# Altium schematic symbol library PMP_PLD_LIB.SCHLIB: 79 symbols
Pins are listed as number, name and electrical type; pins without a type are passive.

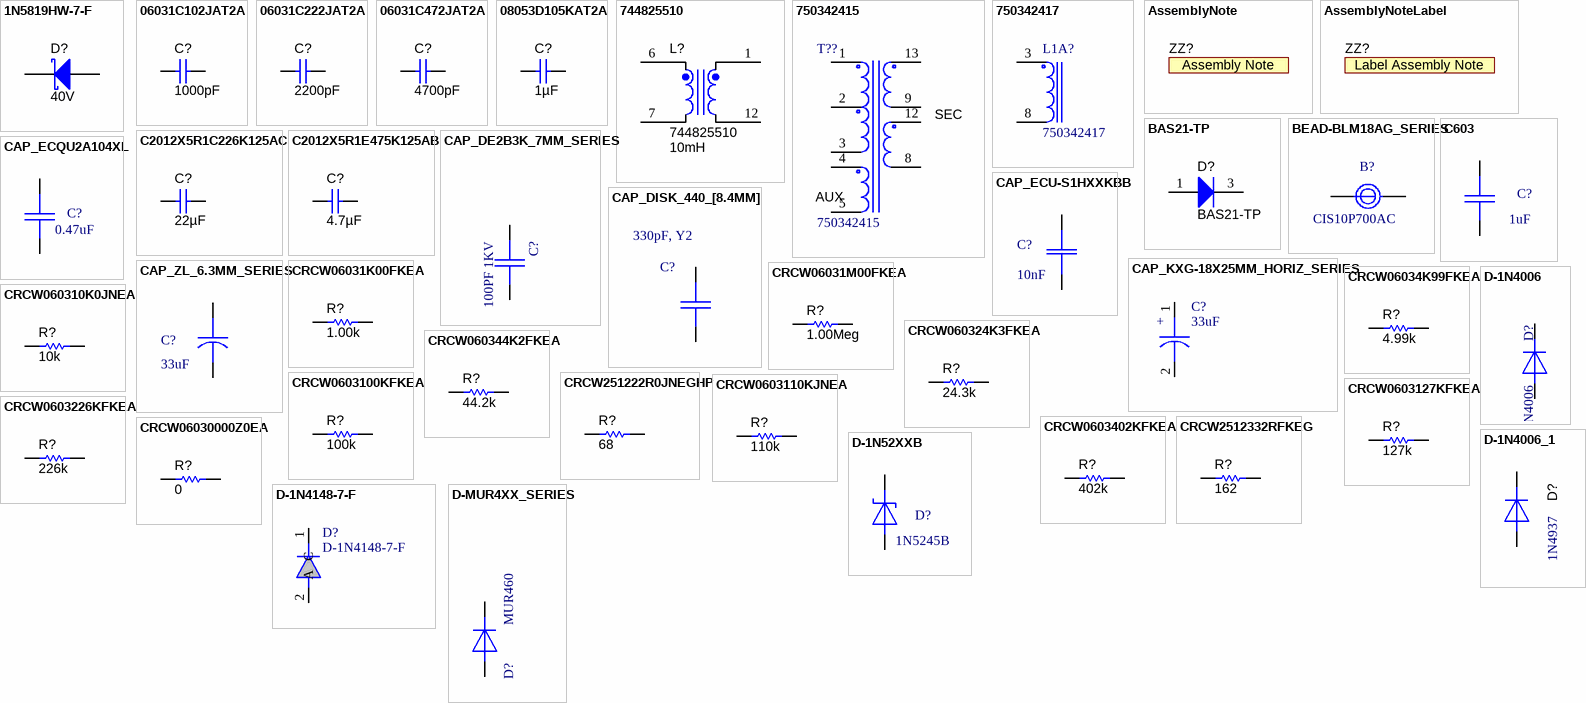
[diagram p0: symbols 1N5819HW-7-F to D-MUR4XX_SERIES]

## 1N5819HW-7-F
designator D?  value 40V  (hidden comment: 1N5819HW-7-F)
Diode, Schottky, 40V, 1A, SOD-123; Manufacturer: Diodes Inc.; U/M: EA; Vf_V: 0.45; Value2: 0.45V; Io_A: 1; Vr_V: 40; TJmax_C: 125
signal-integrity model Diode
simulation model DI_1N5819HW
footprint SOD-123
pins: 1 K, 2 A

## 06031C102JAT2A
designator C?  ValueDisplayed: 1000pF  (hidden comment: 06031C102JAT2A)
CAP, CERM, 1000pF, 100V, +/-5%, X7R, 0603; Manufacturer: AVX; Polarized: N; CompType: Capacitor; U/M: EA; Cap_F: 0.000000001; Tolerance_%: 5; ESR_Ohm: 0.276; Value1: 0.276 ohm; VDC_V: 100; TaMin_C: -55; TaMax_C: 125; Cap_Case: 0603
signal-integrity model Cap
simulation model Cap
footprint 0603
footprint 0603M
footprint 0603L
footprint 0603_HV
footprint 0603S
pins: 1, 2

## 06031C222JAT2A
designator C?  ValueDisplayed: 2200pF  (hidden comment: 06031C222JAT2A)
CAP, CERM, 2200pF, 100V, +/-5%, X7R, 0603; Manufacturer: AVX; Polarized: N; CompType: Capacitor; U/M: EA; Cap_F: 0.0000000022; Tolerance_%: 5; ESR_Ohm: 0.192; Value1: 0.192 ohm; VDC_V: 100; TaMin_C: -55; TaMax_C: 125; Cap_Case: 0603
signal-integrity model Cap
simulation model Cap
footprint 0603
footprint 0603M
footprint 0603L
footprint 0603_HV
footprint 0603S
pins: 1, 2

## 06031C472JAT2A
designator C?  ValueDisplayed: 4700pF  (hidden comment: 06031C472JAT2A)
CAP, CERM, 4700pF, 100V, +/-5%, X7R, 0603; Manufacturer: AVX; Polarized: N; CompType: Capacitor; U/M: EA; Cap_F: 0.0000000047; Tolerance_%: 5; ESR_Ohm: 0.136; Value1: 0.136 ohm; VDC_V: 100; TaMin_C: -55; TaMax_C: 125; Cap_Case: 0603
signal-integrity model Cap
simulation model Cap
footprint 0603
footprint 0603M
footprint 0603L
footprint 0603_HV
footprint 0603S
pins: 1, 2

## 08053D105KAT2A
designator C?  ValueDisplayed: 1µF  (hidden comment: 08053D105KAT2A)
CAP, CERM, 1uF, 25V, +/-10%, X5R, 0805; Manufacturer: AVX; Polarized: N; CompType: Capacitor; U/M: EA; Cap_F: 0.000001; Tolerance_%: 10; ESR_Ohm: 0.012; Value1: 0.012 ohm; VDC_V: 25; TaMin_C: -55; TaMax_C: 85; Cap_Case: 0805
signal-integrity model Cap
simulation model Cap
footprint 0805_HV
footprint 0805
footprint 0805M
footprint 0805L
pins: 1, 2

## 744825510
designator L?  ValueDisplayed: 10mH
Coupled inductor, 10mH, 5A, 0.055 ohm, TH; Manufacturer: Wurth Elektronik eiSos; SymbolCreator: a0799628; Ind_H: 10.0E-3; DCR_ohm: 0.055; Isat: 5
footprint WE-CMB_XL
pins: 1, 6, 7, 12

## 750342415
designator T??
TRANSFOERMER, 856uH, +/-10%, TH, 14-PIN; Manufacturer: WURTH ELEKTRONIK; CompType: TRANSFORMER; SymbolCreator: x0199378
footprint WE_750342415 (TRANSFOERMER, TH)
pins: 1, 2, 3, 4, 5, 8, 9, 12, 13

## 750342417
designator L1A?
TRANSFOERMER, 300uH, +/-10%, TH, 10-PIN; Manufacturer: WURTH ELEKTRONIK; CompType: TRANSFORMER; SymbolCreator: x0199378
footprint WE_750342417 (TRANSFOERMER, TH)
pins: 3, 8

## AssemblyNote
designator ZZ?  (no BOM)
These assemblies are ESD sensitive, ESD precautions shall be observed.; Part_Number: Part Number; SymbolCreator: codlsc; CompType: AssemblyNote
footprint AssemblyNote

## AssemblyNoteLabel
designator ZZ?  (no BOM)
This Assembly Note is for PCB labels only; Part_Number: Part Number; SymbolCreator: a0412235
footprint AssemblyNoteLabel

## BAS21-TP
designator D?
Diode, P-N, 200V, 200A, SOT-23; Manufacturer: Micro Commercial Components; U/M: EA; Vf_V: 1.25; Value2: 1.25V; Io_A: 200; TJmax_C: 150; RJC_CperW: 430
signal-integrity model Model Name (Model Description)
footprint SOT-23
footprint SOT-23M
footprint SOT-23L
pins: 1 A, 3 K

## BEAD-BLM18AG_SERIES
designator B?, comment CIS10P700AC
FERRITE CHIP 70 OHM 4000MA 0603; Manufacturer: Samsung; Second Source: C:\program files\p-cad 2004\pcad_pdf's\Bead BML SERIES.pdf; Reference: \\vette02\pmp_pcb\pcad_pdf's\Bead BML SERIES.pdf; Area: 5.87 mm; Value: 70ohm; PCB DECAL: 0603
footprint xxxx (Footprint not found)
footprint 0603 (0603 from SM-752 data)
pins: 1, 2

## C603
designator C?  value 1uF  (hidden comment: C603)
CAP CER 1UF 25V 10% X7R 0603; Manufacturer: Kemet; PartNumber: C0603C105K3RACTU; Area: 5650
footprint C603
pins: 1, 2

## C2012X5R1C226K125AC
designator C?  ValueDisplayed: 22µF  (hidden comment: C2012X5R1C226K125AC)
CAP, CERM, 22uF, 16V, +/-10%, X5R, 0805; Manufacturer: TDK; Polarized: N; CompType: Capacitor; U/M: EA; Cap_F: 0.000022; Tolerance_%: 10; Value1: Unknown; VDC_V: 16; TaMin_C: -55; TaMax_C: 85; Cap_Case: 0805
signal-integrity model Cap
simulation model Cap
footprint 0805_HV
footprint 0805
footprint 0805M
footprint 0805L
pins: 1, 2

## C2012X5R1E475K125AB
designator C?  ValueDisplayed: 4.7µF  (hidden comment: C2012X5R1E475K125AB)
CAP, CERM, 4.7uF, 25V, +/-10%, X5R, 0805; Manufacturer: TDK; Polarized: N; CompType: Capacitor; U/M: EA; Cap_F: 0.0000047; Tolerance_%: 10; Value1: Unknown; VDC_V: 25; TaMin_C: -55; TaMax_C: 85; Cap_Case: 0805
signal-integrity model Cap
simulation model Cap
footprint 0805_HV
footprint 0805
footprint 0805M
footprint 0805L
pins: 1, 2

## CAP_DE2B3K_7MM_SERIES
designator C?  value 100PF 1KV  (hidden comment: CAP_DE2B3K_7MM_SERIES)
CAP CER 100PF 1KV 10% RADIAL; PartNumber: DEBB33A101KP2A; Manufacturer: muRata; Area: 48.60 mm; PCB DECAL: CAP_200MIL-A
footprint CAP_200MIL-A
pins: 1, 2

## CAP_DISK_440_[8.4MM]
designator C?  value 330pF, Y2  (hidden comment: CAP_DISK_440_[8.4MM])
CAP CER 330PF 300VAC 10% RADIAL; Manufacturer: Vishay; Part_Number: VY2331K29Y5SS63V7; PartNumber: Part Number; Description: Capacitor, 300VAC, X1Y2, ±10%; Area: 103.50 mm; Reference: \\vette02\pmp_pcb\pcad_pdf's\440l.pdf; Second_Source: C:\program files\p-cad 2004\pcad_pdf's\ABB0000CE12.pdf; Type: CAP_DISK_720; PCB DECAL: CAP_DISK_8.4MM; Second Source: C:\program files\p-cad2004pcad_pdf's\440l.pdf
footprint CAP_DISK_8.4MM
pins: 1, 2

## CAP_ECQU2A104XL
designator C?, comment value 0.47uF  (hidden comment: R46KI347050P1M)
CAP FILM 0.47UF 560VDC RADIAL; Manufacturer: Kemet; PCB DECAL: 18.00mm x 9.00mm; Area: 97500
footprint CAP_591MIL
pins: 1, 2

## CAP_ECU-S1HXXKBB
designator C?  value 10nF  (hidden comment: CAP_ECU-S1HXXKBB)
CAP CER 10000PF 1KV 20% RADIAL; Manufacturer: Vishay; PartNumber: S103M47Z5UN63J7R; Part_Number: Part Number; Area: 43200; Reference: \\vette02\pmp_pcb\pcad_pdf's\panasonic_ECQu.pdf; Second_Source: C:\program files\p-cad 2004\pcad_pdf's\panasonic_ECQu.pdf; PCB DECAL: CAP_200MIL
footprint CAP_200MIL
pins: 1, 2

## CAP_KXG-18X25MM_HORIZ_SERIES
designator C?, comment 33uF
Capacitor, Electrolytic, -40 to +105 °C; PartNumber: EKXG451ELL330MM20S; Manufacturer: Nippon; Area: 667.40 mm; Value: xx uH
footprint CAP_18X25MM7.5_PITCH_HORIZ
pins: 1, 2
1 alternate drawing of the same symbol

## CAP_ZL_6.3MM_SERIES
designator C?  value 33uF  (hidden comment: CAP_ZL_6.3MM_SERIES)
CAP ALUM 33UF 35V 20% RADIAL; Manufacturer: Rubycon; Part_Number: 35YXJ33M5X11; PartNumber: Part Number; Area: 70,686; Type: CAP_ZL_6.3MM SERIES; PCB DECAL: CAP_ZL-6.3MM
footprint CAP_ZL-6.3MM
pins: 1, 2

## CRCW06031K00FKEA
designator R?  value 1.00k  (hidden comment: CRCW06031K00FKEA)
RES, 1.00k ohm, 1%, 0.1W, 0603; Manufacturer: Vishay-Dale; CompType: Resistor; Res_ohm: 1000; Value_Code: 1k00; Tolerance_%: 1; Power_W: 0.1; VDC_V: 75; TempCo: 100 ppm/C; EIA_Code: E96; U/M: EA
signal-integrity model Resistor
simulation model Resistor
footprint 0603
footprint 0603M
footprint 0603L
footprint 0603_HV
footprint 0603S
pins: 1, 2

## CRCW06031M00FKEA
designator R?  value 1.00Meg  (hidden comment: CRCW06031M00FKEA)
RES, 1.00Meg ohm, 1%, 0.1W, 0603; Manufacturer: Vishay-Dale; CompType: Resistor; Res_ohm: 1000000; Value_Code: 1M00; Tolerance_%: 1; Power_W: 0.1; VDC_V: 75; TempCo: 100 ppm/C; EIA_Code: E96; U/M: EA
signal-integrity model Resistor
simulation model Resistor
footprint 0603
footprint 0603M
footprint 0603L
footprint 0603_HV
footprint 0603S
pins: 1, 2

## CRCW06034K99FKEA
designator R?  value 4.99k  (hidden comment: CRCW06034K99FKEA)
RES, 4.99k ohm, 1%, 0.1W, 0603; Manufacturer: Vishay-Dale; CompType: Resistor; Res_ohm: 4990; Value_Code: 4k99; Tolerance_%: 1; Power_W: 0.1; VDC_V: 75; TempCo: 100 ppm/C; EIA_Code: E96; U/M: EA
signal-integrity model Resistor
simulation model Resistor
footprint 0603
footprint 0603M
footprint 0603L
footprint 0603_HV
footprint 0603S
pins: 1, 2

## CRCW060310K0JNEA
designator R?  value 10k  (hidden comment: CRCW060310K0JNEA)
RES, 10k ohm, 5%, 0.1W, 0603; Manufacturer: Vishay-Dale; CompType: Resistor; Res_ohm: 10000; Value_Code: 10k0; Tolerance_%: 5; Power_W: 0.1; VDC_V: 75; TempCo: 200 ppm/C; EIA_Code: E24; U/M: EA
signal-integrity model Resistor
simulation model Resistor
footprint 0603
footprint 0603M
footprint 0603L
footprint 0603_HV
footprint 0603S
pins: 1, 2

## CRCW060324K3FKEA
designator R?  value 24.3k  (hidden comment: CRCW060324K3FKEA)
RES, 24.3k ohm, 1%, 0.1W, 0603; Manufacturer: Vishay-Dale; CompType: Resistor; Res_ohm: 24300; Value_Code: 24k3; Tolerance_%: 1; Power_W: 0.1; VDC_V: 75; TempCo: 100 ppm/C; EIA_Code: E96; U/M: EA
signal-integrity model Resistor
simulation model Resistor
footprint 0603
footprint 0603M
footprint 0603L
footprint 0603_HV
footprint 0603S
pins: 1, 2

## CRCW060344K2FKEA
designator R?  value 44.2k  (hidden comment: CRCW060344K2FKEA)
RES, 44.2k ohm, 1%, 0.1W, 0603; Manufacturer: Vishay-Dale; CompType: Resistor; Res_ohm: 44200; Value_Code: 44k2; Tolerance_%: 1; Power_W: 0.1; VDC_V: 75; TempCo: 100 ppm/C; EIA_Code: E96; U/M: EA
signal-integrity model Resistor
simulation model Resistor
footprint 0603
footprint 0603M
footprint 0603L
footprint 0603_HV
footprint 0603S
pins: 1, 2

## CRCW251222R0JNEGHP
designator R?, comment value 68  (hidden comment: RHC2512FT68R0)
RES 68 OHM 2W 1% 2512; Manufacturer: Stackpole Electronics Inc; CompType: Resistor; Tolerance_%: 1
signal-integrity model Resistor
simulation model Resistor
footprint 2512M
footprint 2512L
footprint 2512
pins: 1, 2

## CRCW0603100KFKEA
designator R?  value 100k  (hidden comment: CRCW0603100KFKEA)
RES, 100k ohm, 1%, 0.1W, 0603; Manufacturer: Vishay-Dale; CompType: Resistor; Res_ohm: 100000; Tolerance_%: 1; Power_W: 0.1; VDC_V: 75; TempCo: 100 ppm/C; EIA_Code: E96; U/M: EA
signal-integrity model Resistor
simulation model Resistor
footprint 0603
footprint 0603M
footprint 0603L
footprint 0603_HV
footprint 0603S
pins: 1, 2

## CRCW0603110KJNEA
designator R?  value 110k  (hidden comment: CRCW0603110KJNEA)
RES, 110k ohm, 5%, 0.1W, 0603; Manufacturer: Vishay-Dale; CompType: Resistor; Res_ohm: 110000; Tolerance_%: 5; Power_W: 0.1; VDC_V: 75; TempCo: 200 ppm/C; EIA_Code: E24; U/M: EA
signal-integrity model Resistor
simulation model Resistor
footprint 0603
footprint 0603M
footprint 0603L
footprint 0603_HV
footprint 0603S
pins: 1, 2

## CRCW0603127KFKEA
designator R?  value 127k  (hidden comment: CRCW0603127KFKEA)
RES, 127k ohm, 1%, 0.1W, 0603; Manufacturer: Vishay-Dale; CompType: Resistor; Res_ohm: 127000; Tolerance_%: 1; Power_W: 0.1; VDC_V: 75; TempCo: 100 ppm/C; EIA_Code: E96; U/M: EA
signal-integrity model Resistor
simulation model Resistor
footprint 0603
footprint 0603M
footprint 0603L
footprint 0603_HV
footprint 0603S
pins: 1, 2

## CRCW0603226KFKEA
designator R?  value 226k  (hidden comment: CRCW0603226KFKEA)
RES, 226k ohm, 1%, 0.1W, 0603; Manufacturer: Vishay-Dale; CompType: Resistor; Res_ohm: 226000; Tolerance_%: 1; Power_W: 0.1; VDC_V: 75; TempCo: 100 ppm/C; EIA_Code: E96; U/M: EA
signal-integrity model Resistor
simulation model Resistor
footprint 0603
footprint 0603M
footprint 0603L
footprint 0603_HV
footprint 0603S
pins: 1, 2

## CRCW0603402KFKEA
designator R?  value 402k  (hidden comment: CRCW0603402KFKEA)
RES, 402k ohm, 1%, 0.1W, 0603; Manufacturer: Vishay-Dale; CompType: Resistor; Res_ohm: 402000; Tolerance_%: 1; Power_W: 0.1; VDC_V: 75; TempCo: 100 ppm/C; EIA_Code: E96; U/M: EA
signal-integrity model Resistor
simulation model Resistor
footprint 0603
footprint 0603M
footprint 0603L
footprint 0603_HV
footprint 0603S
pins: 1, 2

## CRCW2512332RFKEG
designator R?, comment value 162  (hidden comment: CRCW2512162RFKEGHP)
RES 162 OHM 1.5W 1% 2512 SMD; Manufacturer: Vishay-Dale; CompType: Resistor; Value_Code: 162R; Tolerance_%: 1; EIA_Code: E96; U/M: EA
signal-integrity model Resistor
simulation model Resistor
footprint 2512M
footprint 2512L
footprint 2512
pins: 1, 2

## CRCW06030000Z0EA
designator R?  value 0  (hidden comment: CRCW06030000Z0EA)
RES, 0 ohm, 5%, 0.1W, 0603; Manufacturer: Vishay-Dale; CompType: Resistor; Value_Code: 0000; Tolerance_%: 5; Power_W: 0.1; VDC_V: 75; TempCo: 200 ppm/C; EIA_Code: E24; U/M: EA
signal-integrity model Resistor
simulation model Resistor
footprint 0603
footprint 0603M
footprint 0603L
footprint 0603_HV
footprint 0603S
pins: 1, 2

## D-1N52XXB
designator D?  value 1N5245B  (hidden comment: D-1N52XXB)
DIODE, Zener, 15V, .5W, 5%; PartNumber: 1N5245BTR; Manufacturer: Fairchild; Area: 64900; PCB DECAL: DO-35; Second Source: C:\program files\p-cad 2004\pcad_pdf's\1N52xx_DO-35.pdf; Reference: \\vette02\pmp_pcb\pcad_pdf's\1N52xx_DO-35.pdf
footprint DO-35
pins: 1 C, 2 A

## D-1N4006
designator D?  value 1N4006  (hidden comment: D-1N4006)
Diode, Rectifier, 800V, 1A; PartNumber: 1N4006-T; Manufacturer: Diodes; Part_Number: Part Number; Second Source: C:\program files\p-cad 2004\pcad_pdf's\1N400x.pdf; Reference: \\vette02\pmp_pcb\pcad_pdf's\1N400x.pdf; Area: 54000; PCB DECAL: DO-41
footprint DO-41 (diode)
pins: 1 C, 2 A

## D-1N4006_1
designator D?, comment value 1N4937  (hidden comment: D-1N4006)
Diode, Fast, 600V, 1A; Manufacturer: Fairchild; Part_Number: Part Number; Second Source: C:\program files\p-cad 2004\pcad_pdf's\1N400x.pdf; Reference: \\vette02\pmp_pcb\pcad_pdf's\1N400x.pdf; Area: 54000; PCB DECAL: DO-41_VERT
pins: 1 A, 2 C

## D-1N4148-7-F
designator D?
Diode, Signal, 300-mA, 75-V, 350-mW; PartNumber: 1N4148W-7-F; Manufacturer: Diodes; Area: 13300; Value: 1N4148W-7-F
footprint D_SOD123
pins: 1 C, 2 A

## D-MUR4XX_SERIES
designator D?  value MUR460  (hidden comment: D-MUR4XX_SERIES)
Diode, Utrafast, Power Rectifier, 600V, 4A; PartNumber: MUR460RLG; Manufacturer: OnSemi; Part_Number: Part Number; Second Source: C:\program files\p-cad 2004\pcad_pdf's\MUR4xx series.pdf; Reference: \\vette02\pmp_pcb\pcad_pdf's\MUR4xx series.pdf; Area: 96800; PCB DECAL: DO-201AD
footprint DO-201AD (Vishay dimensions)
pins: 1, 2

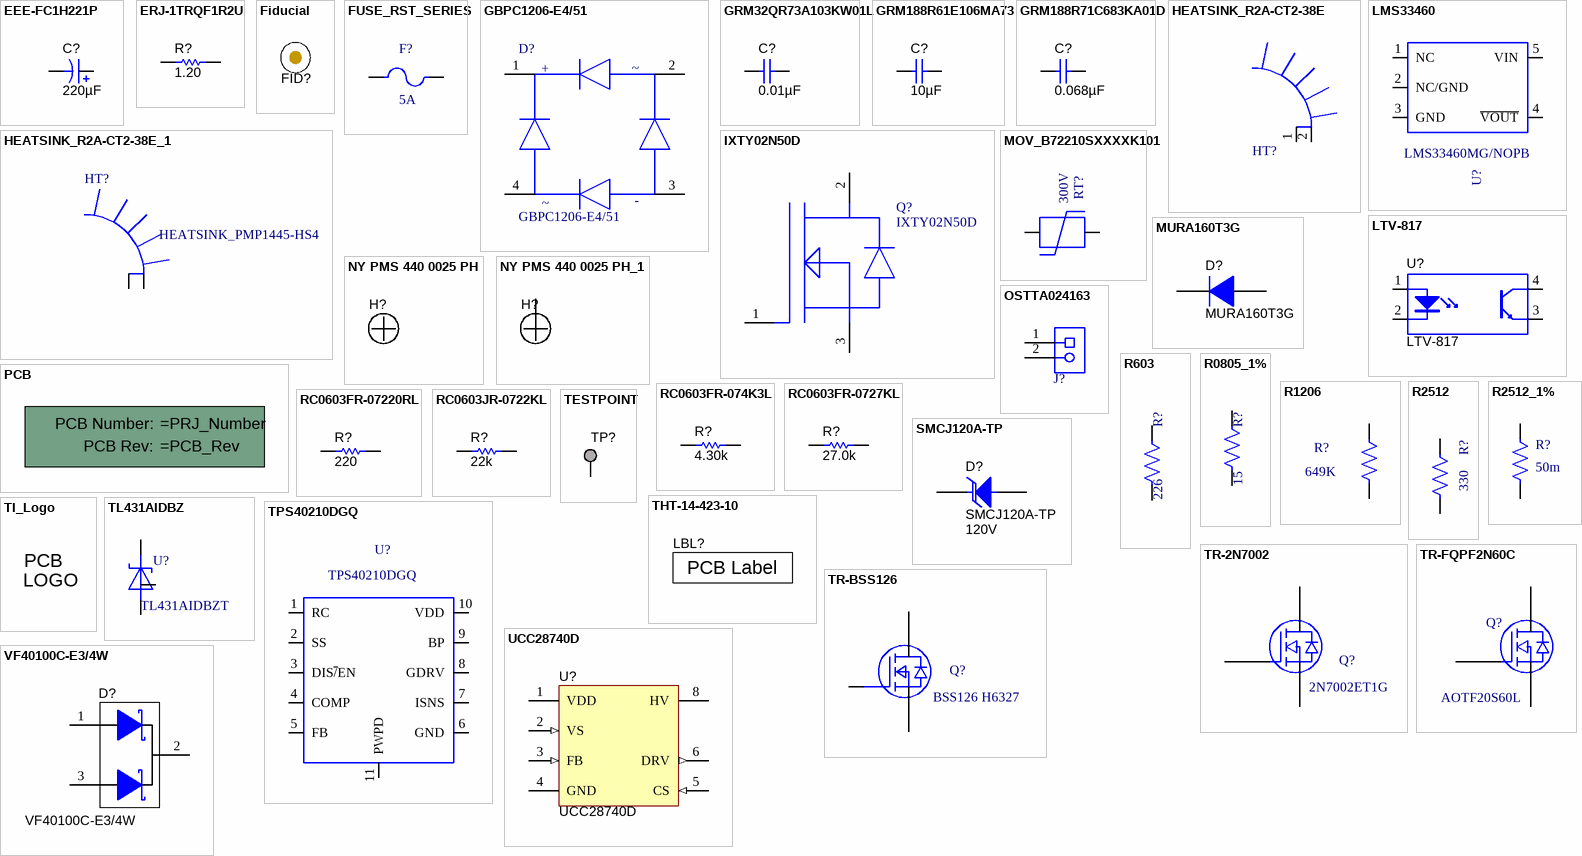
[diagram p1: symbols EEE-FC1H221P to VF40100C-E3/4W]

## EEE-FC1H221P
designator C?  ValueDisplayed: 220µF  (hidden comment: EEE-FC1H221P)
CAP, AL, 220uF, 50V, +/-20%, 0.3 ohm, SMD; Manufacturer: Panasonic; Polarized: Y; CompType: Capacitor; U/M: EA; Cap_F: 0.00022; Tolerance_%: 20; Value1: 0.3 ohm; VDC_V: 50; ESR_Ohm: 0.3; IRMS_A: 0.5; TaMin_C: -40; TaMax_C: 105; Cap_Case: G
signal-integrity model Cap
simulation model Cap
footprint SM_RADIAL_G
pins: 1 +, 2 -

## ERJ-1TRQF1R2U
designator R?  value 1.20  (hidden comment: ERJ-1TRQF1R2U)
RES, 1.20 ohm, 1%, 1W, 2512; Manufacturer: Panasonic; CompType: Resistor; Res_ohm: 1.2; Value_Code: 1R20; Tolerance_%: 1; TempCo: 100 ppm/C; U/M: EA
signal-integrity model Resistor
simulation model Resistor
footprint 2512M
footprint 2512L
footprint 2512
pins: 1, 2

## Fiducial
designator FID?  (value not drawn)
Fiducial mark.  There is nothing to buy or mount.; Part_Number: Part Number; SymbolCreator: codlsc
footprint Fiducial10-30
footprint Fiducial10-20
footprint Fiducial15-30
footprint Fiducial20-40
footprint Fiducial6.4-20
footprint Fiducial10-30_Panel

## FUSE_RST_SERIES
designator F?  value 5A  (hidden comment: FUSE_RST_SERIES)
FUSE SLOW 250VAC 5A RADIAL; Manufacturer: BEL; PartNumber: RST 5; Area: 43.2 mm; PCB DECAL: FUSE_4X8.5-5.08P; Reference: \\vette02\pmp_pcb\pcad_pdf's\RST.pdf; Second Source: C:\program files\p-cad 2004\pcad_pdf's\RST.pdf
footprint FUSE_4X8.5-5.08P
pins: 1, 2

## GBPC1206-E4/51
designator D?
DISCRETE, RECTIFIER BRIDGE 12A 600V, GBPC-4; Manufacturer: VISHAY SEMICONDUCTOR; SymbolCreator: X0199378
footprint MODULE_GBPC1206W-E4-51
pins: 1, 2, 3, 4

## GRM32QR73A103KW01L
designator C?  ValueDisplayed: 0.01µF  (hidden comment: GRM32QR73A103KW01L)
CAP, CERM, 0.01uF, 1000V, +/-10%, X7R, 1210; Manufacturer: MuRata; Polarized: N; CompType: Capacitor; U/M: EA; Cap_F: 0.00000001; Tolerance_%: 10; Value1: Unknown; VDC_V: 1000; TaMin_C: -55; TaMax_C: 125; Cap_Case: 1210
signal-integrity model Cap
simulation model Cap
footprint 1210
footprint 1210M
footprint 1210L
pins: 1, 2

## GRM188R61E106MA73
designator C?  ValueDisplayed: 10µF  (hidden comment: GRM188R61E106MA73)
CAP, CERM, 10uF, 25V, +/-20%, X5R, 0603; Manufacturer: MuRata; Polarized: N; CompType: Capacitor; U/M: EA; Cap_F: 0.00001; Tolerance_%: 20; Value1: Unknown; VDC_V: 25; TaMin_C: -55; TaMax_C: 85; Cap_Case: 0603
signal-integrity model Cap
simulation model Cap
footprint 0603
footprint 0603M
footprint 0603L
footprint 0603_HV
footprint 0603S
pins: 1, 2

## GRM188R71C683KA01D
designator C?  ValueDisplayed: 0.068µF  (hidden comment: GRM188R71C683KA01D)
CAP, CERM, 0.068uF, 16V, +/-10%, X7R, 0603; Manufacturer: MuRata; Polarized: N; CompType: Capacitor; U/M: EA; Cap_F: 0.000000068; Tolerance_%: 10; Value1: Unknown; VDC_V: 16; TaMin_C: -55; TaMax_C: 125; Cap_Case: 0603
signal-integrity model Cap
simulation model Cap
footprint 0603
footprint 0603M
footprint 0603L
footprint 0603_HV
footprint 0603S
pins: 1, 2

## HEATSINK_R2A-CT2-38E
designator HT?, comment HEATSINK_PMP1445-HS4  (value not drawn)
Heatsink, TO-220; Manufacturer: Ohmite; PartNumber: R2A-CT2-38E; PartNumber: Part Number; Value: R2A-CT2-38E
footprint R2A-CT2-38E-ND (HEATSINK FOR TO-220)
pins: 1, 2

## HEATSINK_R2A-CT2-38E_1
designator HT?, comment HEATSINK_PMP1445-HS4
Heatsink, TO-220; Manufacturer: Ohmite; PartNumber: R2A-CT2-38E; PartNumber: Part Number; Value: R2A-CT2-38E
footprint R2A-CT2-38E-ND (HEATSINK FOR TO-220)
pins: 1, 2

## IXTY02N50D
designator Q?
DISCRETE, MOSFET N-CH 500V 200MA, DPAK; Manufacturer: IXYS; SymbolCreator: x0199378
footprint TO228P991X238-3N
pins: 1 G, 2 D, 3 S

## LMS33460
designator U?  value LMS33460MG/NOPB  (hidden comment: LMS33460)
IC DETECTOR UNDER VOLT 3V SC70-5; Manufacturer: TI; Second Source: C:\program files\p-cad 2004\pcad_pdf's\lms33460[1].pdf; Reference: \\vette02\pmp_pcb\pcad_pdf's\lms33460[1].pdf; Area: 12.05 mm; PCB DECAL: SC-70-5
footprint SC-70-5
pins: 1 NC, 2 NC/GND, 3 GND, 4 ~{VOUT}, 5 VIN

## LTV-817
designator U?
Opto-Isolator, 1 Channel, TH; Manufacturer: Lite-On; CompType: OPTOCOUPLER; U/M: EA
footprint DIP762W60P254L460H350Q4B
pins: 1 A, 2 K, 3 E, 4 C

## MOV_B72210SXXXXK101
designator RT?  value 300V  (hidden comment: MOV_B72210SXXXXK101)
MOV, 300V; Manufacturer: Bourns; Part_Number: MOV-10D471KTR; Area: 85,500; PCB DECAL: DISK-472
footprint DISK-472
pins: 1, 2

## MURA160T3G
designator D?
Diode, Ultrafast, 600V, 1A, SMA; Manufacturer: ON Semiconductor; U/M: EA; Vf_V: 1.05; Value2: 1.05V; Io_A: 1; Vr_V: 600; TJmax_C: 175
signal-integrity model Diode
simulation model Dmura160t3
footprint SMA
pins: 1 K, 2 A

## NY PMS 440 0025 PH
designator H?
Mounting Hole M3 3.5mm; Manufacturer: STD; CompType: Hardware; U/M: EA
footprint NY PMS 440 0025 PH

## NY PMS 440 0025 PH_1
designator H?
Mounting Hole M3 3.5mm; Manufacturer: STD; CompType: Hardware; U/M: EA
footprint NY PMS 440 0025 PH
pins: 1

## OSTTA024163
designator J?  (value not drawn)
Terminal Block, 2x1, 5.08mm, TH; PartNumber: OSTTC022162; Manufacturer: On-Shore Technology; SymbolCreator: a0412235; U/M: EA
footprint On-Shore_OSTTA024163
pins: 1, 2

## PCB
designator !PCB?  (mechanical)
Printed Circuit Board; Manufacturer: Any; Part_Number: Part Number; SymbolCreator: a0412235; CompType: PCB
1 alternate drawing of the same symbol

## R603
designator R?  value 226  (hidden comment: R603)
RES 226 OHM 1/10W 1% 0603 SMD; Part_Number: RC0603FR-07226RL; Manufacturer: Yageo; Area: 5650
footprint R603
pins: 1, 2

## R0805_1%
designator R?  value 15  (hidden comment: R0805_1%)
RES 15.0 OHM 1/8W 1% 0805 SMD; Part_Number: RC0805FR-0715RL; Manufacturer: Yageo; Area: 15,300; PCB DECAL: R0805
footprint R0805
pins: 1, 2

## R1206
designator R?  value 649K  (hidden comment: R1206)
RES 649K OHM 1/4W 1% 1206 SMD; Manufacturer: Yageo; PartNumber: RC1206FR-07649KL; Area: 15390
footprint r1206
pins: 1, 2

## R2512
designator R?  value 330  (hidden comment: R2512)
RES 330 OHM 1W 5% 2512; Manufacturer: Samsung; PartNumber: RC6432J331CS; Area: 35100
footprint R2512
pins: 1, 2

## R2512_1%
designator R?  value 50m  (hidden comment: R2512_1%)
RES 0.05 OHM 1W 1% 2512 SMD; Part_Number: LRMAM2512-R05FT4; Manufacturer: TT/Welwyn; PartNumber: LRMAM2512-R02FT4; Area: 56000; PCB DECAL: R2512; Second Source: C:\program files\p-cad 2004\pcad_pdf's\SML-LXR1206USBC-TR[1].pdf; Reference: \\vette02\pmp_pcb\pcad_pdf's\SML-LXR1206USBC-TR[1].pdf
footprint R2512
pins: 1, 2

## RC0603FR-074K3L
designator R?  value 4.30k  (hidden comment: RC0603FR-074K3L)
RES, 4.30k ohm, 1%, 0.1W, 0603; Manufacturer: Yageo America; CompType: Resistor; Res_ohm: 4300; Value_Code: 4k30; Tolerance_%: 1; Power_W: 0.1; VDC_V: 150; TempCo: 200 ppm/C; U/M: EA
signal-integrity model Resistor
simulation model Resistor
footprint 0603
footprint 0603M
footprint 0603L
footprint 0603_HV
footprint 0603S
pins: 1, 2

## RC0603FR-0727KL
designator R?  value 27.0k  (hidden comment: RC0603FR-0727KL)
RES, 27.0k ohm, 1%, 0.1W, 0603; Manufacturer: Yageo America; CompType: Resistor; Res_ohm: 27000; Value_Code: 27k0; Tolerance_%: 1; Power_W: 0.1; VDC_V: 150; TempCo: 200 ppm/C; U/M: EA
signal-integrity model Resistor
simulation model Resistor
footprint 0603
footprint 0603M
footprint 0603L
footprint 0603_HV
footprint 0603S
pins: 1, 2

## RC0603FR-07220RL
designator R?  value 220  (hidden comment: RC0603FR-07220RL)
RES, 220 ohm, 1%, 0.1W, 0603; Manufacturer: Yageo America; CompType: Resistor; Value_Code: 220R; Tolerance_%: 1; Power_W: 0.1; VDC_V: 150; TempCo: 200 ppm/C; U/M: EA
signal-integrity model Resistor
simulation model Resistor
footprint 0603
footprint 0603M
footprint 0603L
footprint 0603_HV
footprint 0603S
pins: 1, 2

## RC0603JR-0722KL
designator R?  value 22k  (hidden comment: RC0603JR-0722KL)
RES, 22k ohm, 5%, 0.1W, 0603; Manufacturer: Yageo America; CompType: Resistor; Res_ohm: 22000; Value_Code: 22k0; Tolerance_%: 5; Power_W: 0.1; VDC_V: 50; TempCo: 100 ppm/C; EIA_Code: E24; U/M: EA
signal-integrity model Resistor
simulation model Resistor
footprint 0603
footprint 0603M
footprint 0603L
footprint 0603_HV
footprint 0603S
pins: 1, 2

## SMCJ120A-TP
designator D?  value 120V
Diode, TVS, Uni, 120V, 1500W, SMC; Manufacturer: Micro Commercial Components; U/M: EA; Power_W: 1500; Vr_V: 120
footprint SMC
pins: 1 K, 2 A

## TESTPOINT
designator TP?  (value not drawn)  (no BOM)
TEST POINT.  No entry in BOM.; PartNumber: Part Number
footprint TESTPOINT
footprint TP_VIA_018RND008
pins: 1

## THT-14-423-10
designator LBL?
Thermal Transfer Printable Labels, 0.650" W x 0.200" H - 10,000 per roll; Manufacturer: Brady; PartNumber: THT-14-423-10; Part_Number: Part Number; SymbolCreator: a0412235; CompType: Label; Note: Size: 0.65" x 0.20 "
footprint Label_650x200

## TI_Logo
designator Logo?  (no BOM)
Texas Instrument Corporate Signature; Part_Number: Part Number; SymbolCreator: codlsc
footprint TI_Stacked_SolderMask_Medium
footprint TI_Stacked_SolderMask_Small
footprint TI_Stacked_Overlay_Medium
footprint TI_Stacked_Overlay_Small
footprint TI_Horizontal_SolderMask_Medium
footprint TI_Horizontal_SolderMask_Small
footprint TI_Horizontal_Overlay_Medium
footprint TI_Horizontal_Overlay_Small
footprint TI_Symbol_SolderMask_Small
footprint TI_Symbol_Overlay_Medium
footprint TI_Symbol_Overlay_Small
footprint TI_Symbol_SolderMask_Medium

## TL431AIDBZ
designator U?  value TL431AIDBZT  (hidden comment: TL431AIDBZ)
IC VREF SHUNT PREC ADJ SOT23-3; Manufacturer: TI; Second Source: C:\program files\p-cad 2004\pcad_pdf's\TL431A-B.pdf; Reference: \\vette02\pmp_pcb\pcad_pdf's\TL431A-B.pdf; Area: 16384; PCB DECAL: SOT-23
footprint SOT-23 (SOT23, 3-Leads, Body 2.9x1.3mm, Pitch 0.95mm, Lead Span 2.5mm, IPC Medium Density)
pins: 1 C, 2 REF, 3 A

## TPS40210DGQ
designator U?
IC REG CTRLR BST FLYBK CM 10MSOP; Manufacturer: TI; PartNumber: TPS40210DGQR; Area: 38400; Reference: \\vette02\pmp_pcb\pcad_pdf's\tps40210.pdf; Second Source: C:\program files\p-cad 2004\pcad_pdf's\tps40210.pdf; PCB DECAL: DGQ_10PWP
footprint DGQ_10PWP
pins: 1 RC, 2 SS, 3 DIS~{/}EN, 4 COMP, 5 FB, 6 GND, 7 ISNS, 8 GDRV, 9 BP, 10 VDD, 11 PWPD

## TR-2N7002
designator Q?  value 2N7002ET1G  (hidden comment: TR-2N7002)
MOSFET N-CH 60V 260MA SOT-23; Manufacturer: OnSemi; Second Source: C:\program files\p-cad 2004\pcad_pdf's\Diodes_2n7002.pdf; Reference: \\vette02\pmp_pcb\pcad_pdf's\Diodes_2n7002.pdf; Area: 14105
footprint SOT-23 (SOT23, 3-Leads, Body 2.9x1.3mm, Pitch 0.95mm, Lead Span 2.5mm, IPC Medium Density)
pins: 1 G, 2 S, 3 D

## TR-BSS126
designator Q?  value BSS126 H6327  (hidden comment: TR-BSS126)
MOSFET N-CH 600V 21MA SOT23; Manufacturer: Infineon; Second Source: C:\program files\p-cad 2004\pcad_pdf's\BSS126.pdf; Reference: \\vette02\pmp_pcb\pcad_pdf's\BSS126.pdf; Area: 14105; PCB DECAL: SOT-23
footprint SOT-23 (SOT23, 3-Leads, Body 2.9x1.3mm, Pitch 0.95mm, Lead Span 2.5mm, IPC Medium Density)
pins: 1 G, 2 S, 3 D

## TR-FQPF2N60C
designator Q?  value AOTF20S60L  (hidden comment: TR-FQPF2N60C)
MOSFET, Nch, 600-V, 20A, 0.199 Ohms; Manufacturer: Alpha&Omega; Area: 65.4 mm; PCB DECAL: TO-220V; Reference: \\vette02\pmp_pcb\pcad_pdf's\FQPF2N60C.pdf; Second Source: C:\program files\p-cad 2004\pcad_pdf's\FQPF2N60C.pdf
footprint TO-220V
pins: 1 G, 2 D, 3 S

## UCC28740D
designator U?
Constant-Voltage, Constant-Current Flyback Controller Using Opto-Coupler Feedback, D0007A; Alternate Manufacturer: None; Manufacturer: Texas Instruments; SymbolCreator: a0412235; CompType: IC; U/M: EA
footprint D0007A_N
footprint D0007A_M
footprint D0007A_L
pins: 1 VDD (power), 2 VS (in), 3 FB (in), 4 GND (power), 5 CS (in), 6 DRV (out), 8 HV (power)

## VF40100C-E3/4W
designator D?
Diode, Schottky, 100V, 20A, TH; Manufacturer: Vishay-Semiconductor; SymbolCreator: a0411947; U/M: EA; Vf_V: 0.73; Value2: 0.73V; Io_A: 20; Vr_V: 100; TJmax_C: 150; RJC_CperW: 2
signal-integrity model Diode
footprint TO-220AB
footprint TO-220AB_HORIZONTAL
footprint TO-220AB_HORIZONTAL_SMT
footprint TO-220AB_100mil
footprint TO-220AB_Horizontal_100mil
pins: 1 A, 2 K, 3 A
